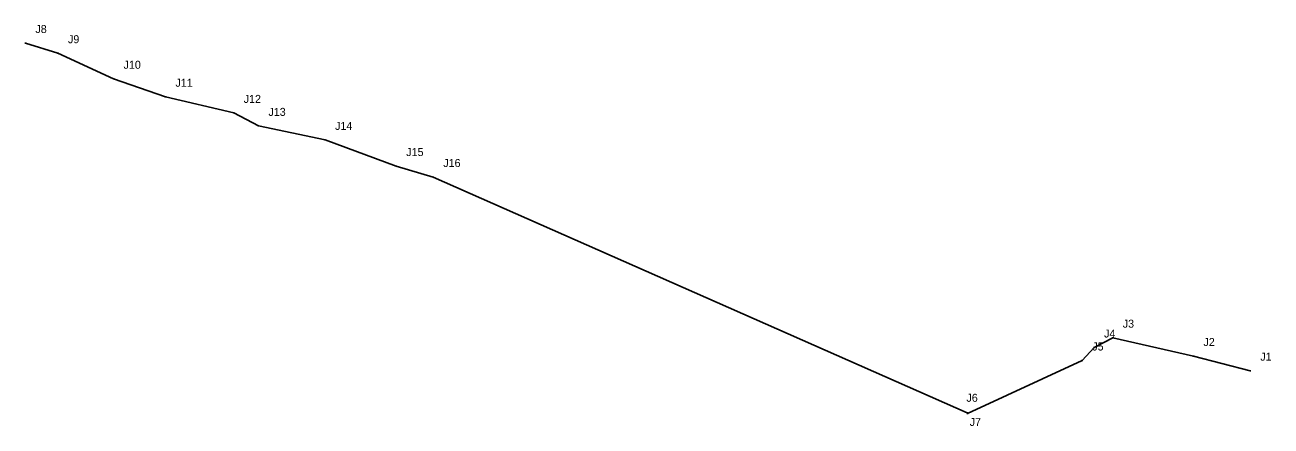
# Model space of a CAD drawing. Extents: x 1728896 to 1729519, y 652699 to 652900.
import ezdxf

# ---------------------------------------------------------------- set-up
doc = ezdxf.new("R2010")
doc.units = 0
for name, color, linetype in [('Level 21', 7, 'Continuous'), ('SURVEY - DRAINAGE - Storm Sewer - Points - Locators', 7, 'Continuous'), ('SURVEY - DRAINAGE - Storm Sewer - Points - Numbers', 7, 'Continuous')]:
    doc.layers.add(name, color=color, linetype=linetype)

msp = doc.modelspace()

# ---------------------------------------------------------------- linework, layer by layer
at = {"layer": 'Level 21'}
for p, q in [((1728896.26, 652890.72), (1728912.54, 652885.64)), ((1728912.54, 652885.64), (1728940.33, 652872.88)), ((1728940.33, 652872.88), (1728966.26, 652863.88)), ((1728966.26, 652863.88), (1729000.38, 652855.8)), ((1729000.38, 652855.8), (1729012.75, 652849.32)), ((1729012.75, 652849.32), (1729046.06, 652842.31)), ((1729046.06, 652842.31), (1729081.64, 652829.24)), ((1729081.64, 652829.24), (1729100.15, 652823.76)), ((1729100.15, 652823.76), (1729367.09, 652705.93)), ((1729430.5, 652738.55), (1729439.81, 652743.46)), ((1729439.81, 652743.46), (1729480.17, 652734.3)), ((1729424.6, 652732.06), (1729430.5, 652738.55)), ((1729367.2, 652705.56), (1729424.6, 652732.06)), ((1729480.17, 652734.3), (1729508.58, 652726.97)), ((1729367.09, 652705.93), (1729367.2, 652705.56)), ((1729367.09, 652705.93), (1729367.2, 652705.56))]:
    msp.add_line(p, q, dxfattribs=at)
at = {"layer": 'SURVEY - DRAINAGE - Storm Sewer - Points - Locators'}
for p, q in [((1728896.51, 652890.72), (1728896.01, 652890.72)), ((1728896.26, 652890.47), (1728896.26, 652890.97)), ((1728896.26, 652890.72), (1728896.26, 652890.72)), ((1728896.26, 652890.72), (1728896.26, 652890.72)), ((1728912.79, 652885.64), (1728912.29, 652885.64)), ((1728912.54, 652885.39), (1728912.54, 652885.89)), ((1728912.54, 652885.64), (1728912.54, 652885.64)), ((1728912.54, 652885.64), (1728912.54, 652885.64)), ((1728940.58, 652872.88), (1728940.08, 652872.88)), ((1728940.33, 652872.63), (1728940.33, 652873.13)), ((1728940.33, 652872.88), (1728940.33, 652872.88)), ((1728940.33, 652872.88), (1728940.33, 652872.88)), ((1728966.51, 652863.88), (1728966.01, 652863.88)), ((1728966.26, 652863.63), (1728966.26, 652864.13)), ((1728966.26, 652863.88), (1728966.26, 652863.88)), ((1728966.26, 652863.88), (1728966.26, 652863.88)), ((1729000.63, 652855.8), (1729000.13, 652855.8)), ((1729000.38, 652855.55), (1729000.38, 652856.05)), ((1729000.38, 652855.8), (1729000.38, 652855.8)), ((1729000.38, 652855.8), (1729000.38, 652855.8)), ((1729013, 652849.32), (1729012.5, 652849.32)), ((1729012.75, 652849.07), (1729012.75, 652849.57)), ((1729012.75, 652849.32), (1729012.75, 652849.32)), ((1729012.75, 652849.32), (1729012.75, 652849.32)), ((1729046.31, 652842.31), (1729045.81, 652842.31)), ((1729046.06, 652842.06), (1729046.06, 652842.56)), ((1729046.06, 652842.31), (1729046.06, 652842.31)), ((1729046.06, 652842.31), (1729046.06, 652842.31)), ((1729081.89, 652829.24), (1729081.39, 652829.24)), ((1729081.64, 652828.99), (1729081.64, 652829.49)), ((1729081.64, 652829.24), (1729081.64, 652829.24)), ((1729081.64, 652829.24), (1729081.64, 652829.24)), ((1729100.4, 652823.76), (1729099.9, 652823.76)), ((1729100.15, 652823.51), (1729100.15, 652824.01)), ((1729100.15, 652823.76), (1729100.15, 652823.76)), ((1729100.15, 652823.76), (1729100.15, 652823.76)), ((1729440.06, 652743.46), (1729439.56, 652743.46)), ((1729439.81, 652743.21), (1729439.81, 652743.71)), ((1729439.81, 652743.46), (1729439.81, 652743.46)), ((1729439.81, 652743.46), (1729439.81, 652743.46)), ((1729430.75, 652738.55), (1729430.25, 652738.55)), ((1729430.5, 652738.3), (1729430.5, 652738.8)), ((1729430.5, 652738.55), (1729430.5, 652738.55)), ((1729430.5, 652738.55), (1729430.5, 652738.55)), ((1729424.85, 652732.06), (1729424.35, 652732.06)), ((1729424.6, 652731.81), (1729424.6, 652732.31)), ((1729424.6, 652732.06), (1729424.6, 652732.06)), ((1729424.6, 652732.06), (1729424.6, 652732.06)), ((1729480.42, 652734.3), (1729479.92, 652734.3)), ((1729480.17, 652734.05), (1729480.17, 652734.55)), ((1729480.17, 652734.3), (1729480.17, 652734.3)), ((1729480.17, 652734.3), (1729480.17, 652734.3)), ((1729508.83, 652726.97), (1729508.33, 652726.97)), ((1729508.58, 652726.72), (1729508.58, 652727.22)), ((1729508.58, 652726.97), (1729508.58, 652726.97)), ((1729508.58, 652726.97), (1729508.58, 652726.97)), ((1729367.34, 652705.93), (1729366.84, 652705.93)), ((1729367.45, 652705.56), (1729366.95, 652705.56)), ((1729367.09, 652705.68), (1729367.09, 652706.18)), ((1729367.09, 652705.93), (1729367.09, 652705.93)), ((1729367.09, 652705.93), (1729367.09, 652705.93)), ((1729367.2, 652705.31), (1729367.2, 652705.81)), ((1729367.2, 652705.56), (1729367.2, 652705.56)), ((1729367.2, 652705.56), (1729367.2, 652705.56))]:
    msp.add_line(p, q, dxfattribs=at)

# ---------------------------------------------------------------- texts
at = {"layer": 'SURVEY - DRAINAGE - Storm Sewer - Points - Numbers'}
for s, p in [('J8', (1728901.26, 652895.72)), ('J9', (1728917.54, 652890.64)), ('J10', (1728945.33, 652877.88)), ('J11', (1728971.26, 652868.88)), ('J12', (1729005.38, 652860.8)), ('J13', (1729017.75, 652854.32)), ('J14', (1729051.06, 652847.31)), ('J15', (1729086.64, 652834.24)), ('J16', (1729105.15, 652828.76)), ('J3', (1729444.81, 652748.46)), ('J4', (1729435.5, 652743.55)), ('J2', (1729485.17, 652739.3)), ('J5', (1729429.6, 652737.06)), ('J1', (1729513.58, 652731.97)), ('J6', (1729366.69, 652711.41)), ('J7', (1729368.3, 652699.34))]:
    msp.add_text(s, height=4, dxfattribs=at).set_placement(p)

doc.saveas('drawing.dxf')
